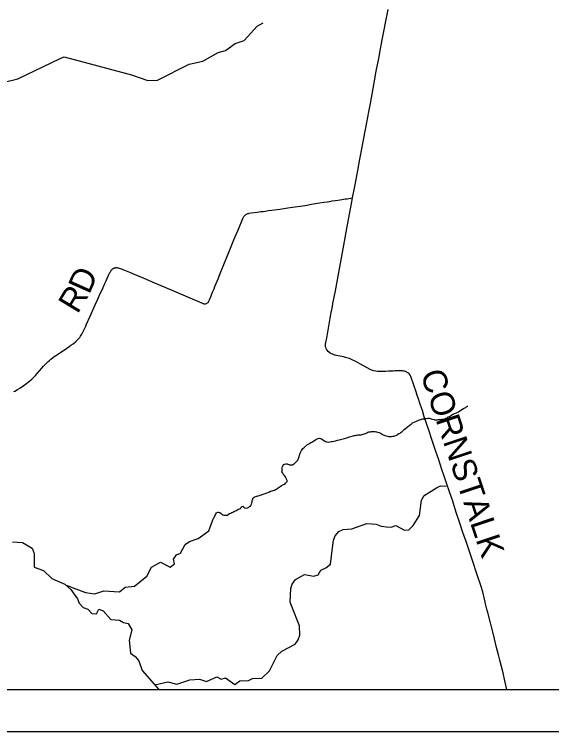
# Model space of a CAD drawing. Extents: x -19.5 to 44.1, y 0 to 22.
# Drawn here: x -16.421 to -15.147, y 14 to 15.7 of the extents above; entities that cross this region are included whole.
import ezdxf

# ---------------------------------------------------------------- set-up
doc = ezdxf.new("R2010")
doc.units = 0
for name, color, linetype in [('GM_X_Minor_River', 7, 'Continuous'), ('GM_X_Township_Road', 7, 'Continuous'), ('GM_X_Township_Road_Text', 7, 'Continuous'), ('SH_Data', 7, 'Continuous')]:
    doc.layers.add(name, color=color, linetype=linetype)

msp = doc.modelspace()

# ---------------------------------------------------------------- linework, layer by layer
at = {"layer": 'GM_X_Minor_River'}
for points in [[(-15.9377, 15.6089), (-15.9206, 15.6144), (-15.8975, 15.6306), (-15.8765, 15.6377), (-15.8454, 15.6719), (-15.8308, 15.6795)], [(-16.6485, 15.5359), (-16.6063, 15.5537), (-16.5938, 15.5526), (-16.5387, 15.5374), (-16.4829, 15.5343), (-16.4483, 15.5381), (-16.4121, 15.5472), (-16.3125, 15.5949), (-16.3029, 15.5992), (-16.1433, 15.5563), (-16.1041, 15.5433), (-16.0813, 15.5436), (-16.0065, 15.5818), (-15.9738, 15.5891), (-15.9377, 15.6089)], [(-15.5067, 14.7076), (-15.504, 14.7095), (-15.5021, 14.7114), (-15.4987, 14.7141), (-15.4967, 14.7159), (-15.4937, 14.7182), (-15.4906, 14.7208), (-15.4887, 14.7223), (-15.4857, 14.7246), (-15.4837, 14.7265), (-15.4818, 14.728), (-15.4795, 14.7295), (-15.4772, 14.7314), (-15.4753, 14.7325), (-15.4719, 14.734), (-15.4692, 14.7351), (-15.4658, 14.7366), (-15.4628, 14.7381), (-15.4605, 14.7389), (-15.4578, 14.7396), (-15.4525, 14.7411), (-15.4498, 14.7415), (-15.4475, 14.7422), (-15.4449, 14.7422), (-15.4407, 14.7425), (-15.438, 14.7425), (-15.4357, 14.7417), (-15.4327, 14.741), (-15.43, 14.7402), (-15.427, 14.7394), (-15.4251, 14.739), (-15.4224, 14.739), (-15.4183, 14.7389), (-15.4156, 14.7393), (-15.4122, 14.7393), (-15.4091, 14.74), (-15.4068, 14.7404), (-15.4049, 14.7404), (-15.4008, 14.7415), (-15.3985, 14.7426), (-15.3954, 14.7437), (-15.3924, 14.7456), (-15.3897, 14.7471), (-15.387, 14.7486), (-15.384, 14.7505), (-15.3809, 14.7524), (-15.3782, 14.7539), (-15.3756, 14.755), (-15.3733, 14.7557), (-15.371, 14.7565), (-15.3679, 14.758), (-15.3653, 14.7602), (-15.3561, 14.7655), (-15.3534, 14.767), (-15.3511, 14.7681), (-15.3485, 14.7704), (-15.3466, 14.7715), (-15.3462, 14.7715)], [(-15.7684, 14.6324), (-15.7661, 14.632), (-15.7642, 14.6319), (-15.7619, 14.6319), (-15.7596, 14.6338), (-15.7577, 14.6346), (-15.7551, 14.6372), (-15.7516, 14.6406), (-15.7493, 14.6432), (-15.7482, 14.6455), (-15.7466, 14.6485), (-15.7458, 14.6512), (-15.7451, 14.6554), (-15.7435, 14.6599), (-15.742, 14.6633), (-15.74, 14.666), (-15.7385, 14.6686), (-15.7373, 14.6709), (-15.7351, 14.6724), (-15.7331, 14.6739), (-15.7263, 14.6803), (-15.7232, 14.6818), (-15.7202, 14.6837), (-15.7179, 14.6848), (-15.7156, 14.6863), (-15.7133, 14.6875), (-15.711, 14.689), (-15.7091, 14.6901), (-15.7064, 14.692), (-15.7034, 14.6939), (-15.7011, 14.695), (-15.6976, 14.6953), (-15.695, 14.6949), (-15.6927, 14.6938), (-15.6897, 14.6915), (-15.6859, 14.6888), (-15.6836, 14.6876), (-15.6813, 14.6869), (-15.6794, 14.6865), (-15.6764, 14.6861), (-15.6734, 14.6864), (-15.6703, 14.6872), (-15.6673, 14.6875), (-15.6638, 14.6886), (-15.66, 14.6894), (-15.6547, 14.6905), (-15.6513, 14.6912), (-15.6475, 14.6923), (-15.6444, 14.6931), (-15.6414, 14.6938), (-15.6383, 14.6949), (-15.6353, 14.6956), (-15.633, 14.6964), (-15.6265, 14.6982), (-15.6235, 14.6994), (-15.62, 14.7001), (-15.6181, 14.7008), (-15.6151, 14.7016), (-15.6132, 14.702), (-15.6109, 14.7023), (-15.6086, 14.7027), (-15.6063, 14.703), (-15.6044, 14.7034), (-15.6006, 14.7034), (-15.5987, 14.7037), (-15.5968, 14.7041), (-15.5945, 14.7049), (-15.5915, 14.7056), (-15.5888, 14.7067), (-15.5854, 14.7082), (-15.5827, 14.7093), (-15.5808, 14.7101), (-15.5785, 14.7108), (-15.5766, 14.7108), (-15.5747, 14.7112), (-15.5728, 14.7115), (-15.5702, 14.7115), (-15.5679, 14.7111), (-15.5656, 14.7111), (-15.5626, 14.7107), (-15.5599, 14.7099), (-15.5565, 14.7088), (-15.5546, 14.708), (-15.5512, 14.7061), (-15.5493, 14.7049), (-15.5466, 14.7034), (-15.5447, 14.7026), (-15.5425, 14.7018), (-15.5368, 14.6999), (-15.5341, 14.6995), (-15.5318, 14.6991), (-15.5299, 14.6991), (-15.5269, 14.6994), (-15.5235, 14.6998), (-15.5216, 14.7002), (-15.5193, 14.7009), (-15.517, 14.7016), (-15.5147, 14.7024), (-15.5124, 14.7039), (-15.5094, 14.7062), (-15.5067, 14.7076)], [(-15.9599, 14.4762), (-15.951, 14.4999), (-15.9495, 14.504), (-15.9483, 14.5059), (-15.9476, 14.5078), (-15.9456, 14.5112), (-15.9441, 14.5139), (-15.9433, 14.5161), (-15.9414, 14.5188), (-15.9387, 14.5203), (-15.9368, 14.5203), (-15.9334, 14.5195), (-15.9308, 14.5168), (-15.9289, 14.5153), (-15.9266, 14.5137), (-15.9247, 14.513), (-15.9221, 14.513), (-15.9194, 14.5126), (-15.9171, 14.5125), (-15.9141, 14.5148), (-15.9106, 14.5167), (-15.908, 14.5178), (-15.9053, 14.5193), (-15.9026, 14.5204), (-15.8988, 14.5223), (-15.8942, 14.5242), (-15.89, 14.5268), (-15.887, 14.5283), (-15.8847, 14.529), (-15.8831, 14.5321), (-15.8809, 14.5336), (-15.8789, 14.5343), (-15.8771, 14.532), (-15.8744, 14.5301), (-15.8706, 14.5293), (-15.8679, 14.5304), (-15.8657, 14.5308), (-15.8634, 14.5334), (-15.8607, 14.5361), (-15.8591, 14.5387), (-15.8576, 14.5421), (-15.8568, 14.5448), (-15.8568, 14.5475), (-15.8564, 14.5494), (-15.8556, 14.552), (-15.8545, 14.5543), (-15.8526, 14.5558), (-15.8507, 14.5565), (-15.8484, 14.5569), (-15.8465, 14.5576), (-15.8438, 14.5584), (-15.8419, 14.5588), (-15.8381, 14.5606), (-15.8354, 14.5614), (-15.8335, 14.5617), (-15.8312, 14.5629), (-15.8289, 14.5636), (-15.8267, 14.5643), (-15.824, 14.5651), (-15.8213, 14.5662), (-15.8179, 14.5677), (-15.8141, 14.5696), (-15.8095, 14.5703), (-15.8072, 14.5714), (-15.8045, 14.5726), (-15.8019, 14.5737), (-15.7996, 14.5748), (-15.7977, 14.5763), (-15.7954, 14.5778), (-15.7908, 14.5812), (-15.7877, 14.5831), (-15.7858, 14.5842), (-15.7824, 14.5857), (-15.7801, 14.5868), (-15.7782, 14.5887), (-15.7763, 14.5902), (-15.7744, 14.5925), (-15.774, 14.5948), (-15.7755, 14.5982), (-15.777, 14.6012), (-15.7785, 14.6035), (-15.7807, 14.607), (-15.7834, 14.6104), (-15.7845, 14.6123), (-15.7868, 14.615), (-15.7864, 14.6173), (-15.7864, 14.6199), (-15.7863, 14.6226), (-15.7859, 14.6253), (-15.7855, 14.6279), (-15.7848, 14.6302), (-15.7821, 14.6328), (-15.7802, 14.634), (-15.7771, 14.6347), (-15.7745, 14.6347), (-15.7726, 14.6339), (-15.7703, 14.6331), (-15.7684, 14.6324)], [(-15.9657, 14.1188), (-15.941, 14.1302), (-15.9308, 14.1246), (-15.9201, 14.1278), (-15.8981, 14.1121), (-15.8862, 14.1202), (-15.866, 14.1216), (-15.8561, 14.1259), (-15.8344, 14.1266), (-15.8158, 14.144), (-15.798, 14.1804), (-15.7868, 14.1904), (-15.7553, 14.2072), (-15.7479, 14.2172), (-15.7446, 14.2286), (-15.7449, 14.251), (-15.7632, 14.2963), (-15.7668, 14.307), (-15.7658, 14.3389), (-15.7625, 14.3491), (-15.7543, 14.3603), (-15.7328, 14.3723), (-15.7109, 14.3684), (-15.7006, 14.3712), (-15.6942, 14.3828), (-15.6824, 14.3878), (-15.6719, 14.3967), (-15.6701, 14.41), (-15.6643, 14.4539), (-15.6602, 14.4641), (-15.6517, 14.4741), (-15.6413, 14.4788), (-15.6212, 14.4802), (-15.5853, 14.4931), (-15.5637, 14.4914), (-15.5516, 14.4866), (-15.5391, 14.4852), (-15.5274, 14.4849), (-15.5171, 14.4884), (-15.496, 14.4773), (-15.4861, 14.4786), (-15.4757, 14.4886), (-15.4604, 14.5122), (-15.4558, 14.5489), (-15.4495, 14.5594), (-15.4207, 14.5778), (-15.4111, 14.5825), (-15.3978, 14.5814)], [(-16.2983, 14.3469), (-16.2522, 14.3294), (-16.2299, 14.3262), (-16.2089, 14.3334), (-16.1717, 14.3315), (-16.1579, 14.3426), (-16.1358, 14.3444), (-16.1065, 14.3681), (-16.0955, 14.3895), (-16.074, 14.4016), (-16.0518, 14.3897), (-16.0414, 14.3978), (-16.0435, 14.4089), (-16.0368, 14.419), (-16.0269, 14.4226), (-16.0162, 14.4437), (-16.0059, 14.4506), (-15.9852, 14.4578), (-15.9599, 14.4762)], [(-16.4248, 14.4494), (-16.4013, 14.4481), (-16.3784, 14.4347), (-16.3734, 14.4224), (-16.374, 14.3898), (-16.3518, 14.3817), (-16.3316, 14.363), (-16.3012, 14.3494), (-16.2866, 14.3366), (-16.2711, 14.315), (-16.2671, 14.3046), (-16.2578, 14.2945), (-16.2465, 14.2901), (-16.2373, 14.2797), (-16.2259, 14.279), (-16.2207, 14.2899), (-16.2106, 14.2863), (-16.1924, 14.2658), (-16.1715, 14.2642), (-16.1618, 14.2583), (-16.1512, 14.2562), (-16.1424, 14.2411), (-16.1489, 14.217), (-16.1457, 14.1857), (-16.1345, 14.1783), (-16.126, 14.1682), (-16.1181, 14.1452), (-16.0784, 14.1)], [(-16.0878, 14.1107), (-16.0568, 14.1177), (-16.036, 14.1127), (-16.0047, 14.123), (-15.9822, 14.1244), (-15.9657, 14.1188)]]:
    msp.add_lwpolyline(points, dxfattribs=at)
at = {"layer": 'GM_X_Township_Road'}
for points in [[(-15.6191, 15.2647), (-15.6139, 15.2918), (-15.6071, 15.3297), (-15.602, 15.3566), (-15.5966, 15.3847), (-15.5927, 15.406), (-15.5857, 15.4433), (-15.5809, 15.4683), (-15.5771, 15.4884), (-15.5682, 15.5373), (-15.563, 15.5654), (-15.5573, 15.5953), (-15.5528, 15.6178), (-15.5503, 15.6306), (-15.5488, 15.6391), (-15.5474, 15.647), (-15.5381, 15.6951), (-15.5351, 15.711)], [(-15.9657, 15.0145), (-15.9643, 15.0151), (-15.963, 15.0158), (-15.9618, 15.0167), (-15.9609, 15.0177), (-15.9603, 15.0186), (-15.9597, 15.0197), (-15.9584, 15.023), (-15.9563, 15.0275), (-15.9552, 15.0305), (-15.9542, 15.0328), (-15.9524, 15.0374), (-15.9508, 15.0415), (-15.9475, 15.0496), (-15.9454, 15.0548), (-15.9378, 15.0731), (-15.9311, 15.0899), (-15.9114, 15.1376), (-15.9003, 15.1652), (-15.8897, 15.1904), (-15.8792, 15.2156), (-15.8783, 15.2175), (-15.8774, 15.2194), (-15.8768, 15.2205), (-15.8759, 15.2217), (-15.8747, 15.2232), (-15.8732, 15.2243), (-15.8719, 15.2252), (-15.8702, 15.2262), (-15.8689, 15.2268), (-15.8674, 15.2274), (-15.8659, 15.2279), (-15.8644, 15.2283), (-15.8585, 15.2294), (-15.8456, 15.2311), (-15.8363, 15.2322), (-15.8314, 15.2328), (-15.8252, 15.2337), (-15.8191, 15.2345), (-15.8105, 15.2357), (-15.7914, 15.2384), (-15.7723, 15.2411), (-15.7612, 15.2427), (-15.7373, 15.2463), (-15.7274, 15.2478), (-15.7164, 15.2497), (-15.698, 15.2527), (-15.6876, 15.2543), (-15.6796, 15.2556), (-15.6734, 15.2565), (-15.6673, 15.2574), (-15.6599, 15.2586), (-15.6489, 15.2604), (-15.6366, 15.2622), (-15.6318, 15.2629), (-15.6191, 15.2647)], [(-15.2535, 14.1), (-15.2582, 14.1207), (-15.2627, 14.1395), (-15.2704, 14.1695), (-15.2738, 14.1818), (-15.2782, 14.1997), (-15.2856, 14.2302), (-15.2989, 14.2821), (-15.3008, 14.2899), (-15.3031, 14.2998), (-15.308, 14.3208), (-15.3108, 14.331), (-15.3148, 14.3441), (-15.3245, 14.3736), (-15.3351, 14.4054), (-15.3511, 14.4531), (-15.3568, 14.4696), (-15.3666, 14.499), (-15.3737, 14.5195), (-15.3828, 14.5482), (-15.389, 14.5662), (-15.3976, 14.5915), (-15.4023, 14.6056), (-15.4074, 14.6215), (-15.416, 14.6468), (-15.4225, 14.6662), (-15.4288, 14.6851), (-15.4327, 14.6968), (-15.437, 14.7098), (-15.4446, 14.7322), (-15.4492, 14.7461), (-15.4538, 14.7608), (-15.4581, 14.7737), (-15.4605, 14.781), (-15.4631, 14.7886), (-15.4658, 14.7968), (-15.4684, 14.8051), (-15.4738, 14.821), (-15.4809, 14.8419), (-15.4824, 14.8447), (-15.484, 14.8467), (-15.4859, 14.8485), (-15.4879, 14.8501), (-15.4895, 14.8511), (-15.4906, 14.8517), (-15.4923, 14.8525), (-15.494, 14.8532), (-15.4958, 14.8538), (-15.4982, 14.8544), (-15.5007, 14.8548), (-15.5032, 14.855), (-15.507, 14.8551), (-15.5188, 14.8546), (-15.5231, 14.8544), (-15.5268, 14.8542), (-15.5342, 14.8538), (-15.5416, 14.8535), (-15.5488, 14.8531), (-15.5519, 14.8531), (-15.5556, 14.8532), (-15.5598, 14.8534), (-15.5638, 14.854), (-15.5689, 14.855), (-15.5735, 14.8565), (-15.5775, 14.8582), (-15.5847, 14.8617), (-15.6007, 14.8707), (-15.6112, 14.8768), (-15.619, 14.8806), (-15.6268, 14.8839), (-15.633, 14.8861), (-15.6407, 14.8883), (-15.6484, 14.8898), (-15.6579, 14.8916), (-15.6628, 14.8928), (-15.6691, 14.8951), (-15.6726, 14.897), (-15.6767, 14.9005), (-15.6794, 14.9037), (-15.6807, 14.9057), (-15.6822, 14.9084), (-15.6832, 14.9118), (-15.6833, 14.9152), (-15.683, 14.9183), (-15.6796, 14.9369), (-15.672, 14.9795), (-15.6696, 14.9934), (-15.6668, 15.0075), (-15.6658, 15.0142), (-15.6627, 15.0296), (-15.6599, 15.0448), (-15.6403, 15.1528), (-15.6311, 15.2009), (-15.6209, 15.2552), (-15.6191, 15.2647)], [(-16.4077, 14.8142), (-16.4001, 14.8195), (-16.3945, 14.8234), (-16.3842, 14.8312), (-16.3824, 14.8327), (-16.3802, 14.8346), (-16.3772, 14.8374), (-16.3745, 14.84), (-16.3705, 14.8442), (-16.3663, 14.8489), (-16.3552, 14.8615), (-16.3515, 14.8657), (-16.3475, 14.8701), (-16.3443, 14.8733), (-16.3408, 14.8767), (-16.3376, 14.8796), (-16.334, 14.8828), (-16.326, 14.8887), (-16.3235, 14.8904), (-16.3062, 14.9021), (-16.3018, 14.9051), (-16.2965, 14.9088), (-16.2912, 14.9124), (-16.2867, 14.9155), (-16.2815, 14.9193), (-16.2756, 14.924), (-16.2733, 14.9259), (-16.271, 14.9282), (-16.2682, 14.9314), (-16.2659, 14.9343), (-16.2638, 14.937), (-16.2621, 14.9396), (-16.2608, 14.9417), (-16.2577, 14.9479), (-16.254, 14.9558), (-16.2517, 14.9609), (-16.2494, 14.9659), (-16.2409, 14.9844), (-16.229, 15.011), (-16.2234, 15.0234), (-16.2162, 15.0396), (-16.213, 15.0468), (-16.2106, 15.0524), (-16.2063, 15.0617), (-16.2035, 15.068), (-16.2015, 15.0724), (-16.1984, 15.0792), (-16.1969, 15.0829), (-16.1952, 15.0862), (-16.1943, 15.088), (-16.1932, 15.0899), (-16.1924, 15.0913), (-16.1918, 15.0922), (-16.1911, 15.0931), (-16.1901, 15.0944), (-16.1892, 15.0954), (-16.1879, 15.0965), (-16.1866, 15.0974), (-16.1855, 15.098), (-16.1845, 15.0984), (-16.1835, 15.0988), (-16.1823, 15.0992), (-16.1811, 15.0994), (-16.1801, 15.0995), (-16.1789, 15.0996), (-16.1778, 15.0996), (-16.1763, 15.0994), (-16.1749, 15.0991), (-16.1725, 15.0985), (-16.1702, 15.0977), (-16.1667, 15.0964), (-16.1639, 15.0953), (-16.1477, 15.0885), (-16.1313, 15.0815), (-16.114, 15.0744), (-16.1011, 15.069), (-16.0888, 15.0638), (-16.0494, 15.0471), (-15.9992, 15.0256), (-15.9844, 15.019), (-15.9769, 15.0159), (-15.9749, 15.0151), (-15.9736, 15.0146), (-15.9726, 15.0143), (-15.9715, 15.0141), (-15.9702, 15.0138), (-15.9692, 15.0138), (-15.9679, 15.0139), (-15.9657, 15.0145)], [(-16.4216, 14.8061), (-16.4199, 14.8071), (-16.4135, 14.8108), (-16.4077, 14.8142)]]:
    msp.add_lwpolyline(points, dxfattribs=at)
at = {"layer": 'SH_Data'}
for p, q in [((-19.213, 14.1), (-12.413, 14.1)), ((-19.313, 14), (-12.313, 14))]:
    msp.add_line(p, q, dxfattribs=at)

# ---------------------------------------------------------------- texts
at = {"layer": 'GM_X_Township_Road_Text'}
for s, height, rotation, p in [('D', 0.0568, 65.8484, (-16.2435, 15.0344)), ('R', 0.0568, 58.7782, (-16.2712, 14.9879)), ('CORNSTALK', 0.05682, 288.4704, (-15.459, 14.8482))]:
    msp.add_text(s, height=height, rotation=rotation, dxfattribs=at).set_placement(p)

doc.saveas('drawing.dxf')
